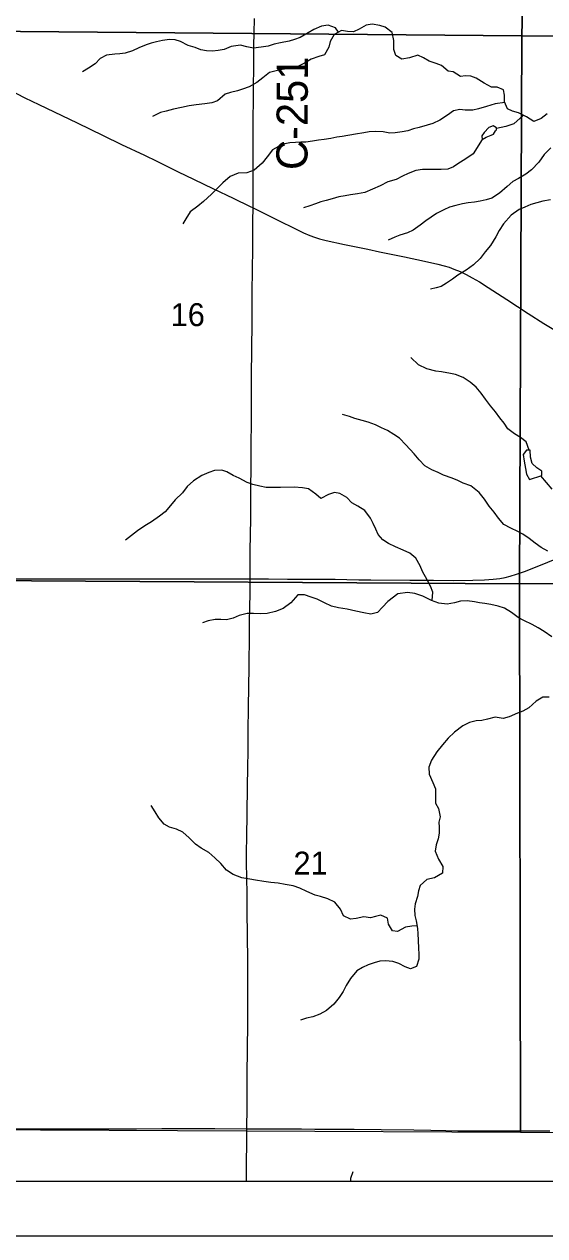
# Model space of a CAD drawing. Extents: x 0 to 34, y 0 to 22.
# Drawn here: x 13.666 to 14.616, y 9.078 to 11.289 of the extents above; entities that cross this region are included whole.
import ezdxf

# ---------------------------------------------------------------- set-up
doc = ezdxf.new("R2010")
doc.units = 0
for name, color, linetype in [('GM_X_County_Road', 7, 'Continuous'), ('GM_X_County_Road_Text', 7, 'Continuous'), ('GM_X_Minor_Lake', 7, 'Continuous'), ('GM_X_Minor_River', 7, 'Continuous'), ('GM_X_Section', 7, 'Continuous'), ('GM_X_Section_Text', 7, 'Continuous'), ('GM_X_Township_Road', 7, 'Continuous'), ('GM_X_US_Route', 7, 'Continuous'), ('SH_Data', 7, 'Continuous')]:
    doc.layers.add(name, color=color, linetype=linetype)

msp = doc.modelspace()

# ---------------------------------------------------------------- linework, layer by layer
at = {"layer": 'GM_X_County_Road'}
for points in [[(14.0833, 10.954), (14.0833, 10.9552), (14.0833, 10.9769), (14.0833, 11.0142), (14.0833, 11.0359), (14.0835, 11.0577), (14.0837, 11.0918), (14.0838, 11.1228), (14.0839, 11.1445), (14.0842, 11.1662), (14.0843, 11.1817), (14.0846, 11.2035), (14.0848, 11.2308), (14.0849, 11.2505), (14.0854, 11.2733), (14.0858, 11.2997)], [(13.4671, 11.2609), (13.4723, 11.2592), (13.478, 11.2569), (13.4823, 11.2551), (13.4923, 11.2503), (13.506, 11.243), (13.5275, 11.2307), (13.5572, 11.2137), (13.5814, 11.1998), (13.6032, 11.1878), (13.6363, 11.1705), (13.6668, 11.1552), (13.6919, 11.1429), (13.762, 11.1094), (13.8094, 11.0862), (13.843, 11.07), (13.8851, 11.05), (13.9075, 11.0392), (13.9465, 11.0201), (13.9745, 11.0065), (14.0109, 10.989), (14.0473, 10.9715), (14.078, 10.9566), (14.0833, 10.954)], [(14.0783, 10.2766), (14.0783, 10.3278), (14.079, 10.3868), (14.0791, 10.4179), (14.0793, 10.4521), (14.0796, 10.4707), (14.0798, 10.4893), (14.0799, 10.5204), (14.0804, 10.5638), (14.0806, 10.6011), (14.0806, 10.6477), (14.0815, 10.7441), (14.0817, 10.772), (14.0818, 10.8), (14.0827, 10.8807), (14.083, 10.9304), (14.0833, 10.954)], [(14.0833, 10.954), (14.1142, 10.9389), (14.1756, 10.9088), (14.187, 10.9036), (14.1958, 10.9003), (14.2047, 10.8976), (14.2168, 10.8945), (14.2503, 10.8875), (14.2928, 10.8784), (14.314, 10.8738), (14.3597, 10.8645), (14.3962, 10.8569), (14.4204, 10.8515), (14.4324, 10.8484), (14.4413, 10.8456), (14.45, 10.8424), (14.4614, 10.8377), (14.4726, 10.8324), (14.4836, 10.8266), (14.4969, 10.8188), (14.5127, 10.8089), (14.5465, 10.7868), (14.5856, 10.7615), (14.6144, 10.7431), (14.6356, 10.7301)], [(14.0721, 9.273), (14.0723, 9.3126), (14.0725, 9.3436), (14.0726, 9.3716), (14.0736, 9.4648), (14.0737, 9.5052), (14.0738, 9.5394), (14.0735, 9.5735), (14.073, 9.6326), (14.0728, 9.6636), (14.0725, 9.6978), (14.0722, 9.7351), (14.0716, 9.7546), (14.0714, 9.7768), (14.0718, 9.8073), (14.0723, 9.8469), (14.0731, 9.8997), (14.0737, 9.9307), (14.0742, 9.9649), (14.0746, 9.999), (14.0752, 10.0425), (14.0757, 10.0797), (14.0761, 10.1153), (14.0763, 10.1353), (14.0766, 10.1572), (14.0768, 10.1775), (14.0771, 10.2012), (14.0774, 10.2222), (14.078, 10.2533), (14.0783, 10.275), (14.0783, 10.2766)], [(14.0713, 9.1775), (14.0713, 9.179), (14.0716, 9.2163), (14.0719, 9.2412), (14.0721, 9.2691), (14.0721, 9.273)]]:
    msp.add_lwpolyline(points, dxfattribs=at)
at = {"layer": 'GM_X_Minor_Lake'}
for points in [[(14.6107, 10.4654), (14.6107, 10.4733), (14.6012, 10.4794), (14.5928, 10.4877), (14.5902, 10.4991), (14.589, 10.512), (14.5829, 10.5116), (14.5765, 10.504), (14.5784, 10.4918), (14.5807, 10.4782), (14.5827, 10.4679), (14.588, 10.4581)], [(14.588, 10.4581), (14.6107, 10.4654)]]:
    msp.add_lwpolyline(points, dxfattribs=at)
at = {"layer": 'GM_X_Minor_River'}
for points in [[(14.2395, 11.275), (14.2336, 11.2827), (14.2203, 11.2875), (14.2081, 11.286), (14.1941, 11.2799), (14.1839, 11.2734), (14.1695, 11.2654), (14.1589, 11.2612), (14.1494, 11.2585), (14.1335, 11.2554), (14.1221, 11.2527), (14.1111, 11.2496), (14.0982, 11.2473), (14.0842, 11.2454), (14.0721, 11.248), (14.0603, 11.251), (14.0436, 11.2487), (14.0307, 11.2433), (14.0197, 11.2414), (14.0095, 11.2399), (13.9985, 11.2406), (13.9879, 11.2428), (13.9776, 11.247), (13.9651, 11.2507), (13.9506, 11.2579), (13.9412, 11.2609), (13.9305, 11.2612), (13.918, 11.2597), (13.907, 11.2574), (13.8975, 11.2547), (13.8881, 11.252), (13.8748, 11.2463), (13.8631, 11.2409), (13.8498, 11.2367), (13.8403, 11.2352), (13.8308, 11.2344), (13.816, 11.2328), (13.8039, 11.2267), (13.7952, 11.2172), (13.7831, 11.2092), (13.7718, 11.2023)], [(14.3946, 11.2277), (14.3839, 11.233), (14.3688, 11.2277), (14.3547, 11.2257), (14.3441, 11.2325), (14.3403, 11.2431), (14.3402, 11.2598), (14.3375, 11.2742), (14.3246, 11.2837), (14.3147, 11.2871), (14.3007, 11.2893), (14.2901, 11.2874), (14.2768, 11.2801), (14.267, 11.2752), (14.256, 11.2763), (14.2446, 11.2778), (14.2313, 11.2705), (14.2242, 11.258), (14.2215, 11.2473), (14.214, 11.2336), (14.2034, 11.2302), (14.1894, 11.2256), (14.1772, 11.218), (14.164, 11.2115), (14.15, 11.2088), (14.1367, 11.2065), (14.1253, 11.2042), (14.1136, 11.2011), (14.1011, 11.1916), (14.0905, 11.1832), (14.0765, 11.1748), (14.0643, 11.1706), (14.0549, 11.1679), (14.0423, 11.1648), (14.0325, 11.1614), (14.0185, 11.1492), (14.0083, 11.1458), (13.995, 11.1438), (13.9794, 11.1422), (13.9665, 11.1403), (13.9529, 11.1376), (13.9381, 11.1342), (13.9248, 11.1307), (13.9142, 11.128), (13.8995, 11.1208)], [(14.6206, 11.1256), (14.6092, 11.1172), (14.596, 11.1119), (14.5823, 11.1202), (14.5678, 11.1273), (14.5572, 11.1307), (14.5477, 11.1349), (14.5427, 11.1474), (14.5427, 11.1599), (14.5404, 11.1694), (14.529, 11.1747), (14.5184, 11.1742), (14.5055, 11.1818), (14.491, 11.1909), (14.4808, 11.1946), (14.4713, 11.195), (14.4618, 11.1942), (14.4489, 11.2025), (14.4394, 11.2036), (14.4272, 11.2142), (14.4174, 11.2176), (14.4048, 11.2217), (14.3946, 11.2277)], [(14.5431, 11.1464), (14.5253, 11.1443), (14.5094, 11.1393), (14.495, 11.1347), (14.4848, 11.1324), (14.4707, 11.1327), (14.4609, 11.1335), (14.4495, 11.1315), (14.4381, 11.1235), (14.4245, 11.1144), (14.4116, 11.1079), (14.401, 11.1048), (14.3866, 11.101), (14.3764, 11.0983), (14.3658, 11.0949), (14.3555, 11.0929), (14.3426, 11.091), (14.3331, 11.0906), (14.3206, 11.0928), (14.3066, 11.0935), (14.2956, 11.0927), (14.2853, 11.0912), (14.2706, 11.0885), (14.2463, 11.0846), (14.2364, 11.0831), (14.2251, 11.0808), (14.2133, 11.0788), (14.2031, 11.0777), (14.1917, 11.0757), (14.1799, 11.0742), (14.1704, 11.0741), (14.161, 11.0737), (14.1507, 11.073), (14.1412, 11.071), (14.1295, 11.0664), (14.1189, 11.06), (14.1091, 11.0474), (14.1, 11.036), (14.0856, 11.023), (14.072, 11.0181), (14.0564, 11.0173), (14.0417, 11.0115), (14.028, 10.9997), (14.0174, 10.9887), (14.0072, 10.9788), (13.9929, 10.9659), (13.9826, 10.9571), (13.9686, 10.9468), (13.9607, 10.9343), (13.955, 10.9248)], [(14.5281, 11.1003), (14.5216, 11.1037), (14.5137, 11.1006), (14.5054, 11.0919), (14.5008, 11.0858), (14.5016, 11.079), (14.5088, 11.0831), (14.5183, 11.087), (14.5224, 11.0885), (14.5258, 11.0946)], [(14.5767, 11.1229), (14.5592, 11.1076), (14.5448, 11.1026), (14.528, 11.0989)], [(14.5258, 11.0946), (14.5278, 11.0966), (14.528, 11.0977), (14.5281, 11.1003)], [(14.5016, 11.079), (14.485, 11.0527), (14.4702, 11.0424), (14.4592, 11.0359), (14.4494, 11.0291), (14.4388, 11.0245), (14.4267, 11.0241), (14.4164, 11.0241), (14.405, 11.0244), (14.3929, 11.024), (14.3808, 11.0224), (14.3664, 11.0171), (14.3561, 11.0117), (14.3444, 11.006), (14.3296, 11.0018), (14.3156, 10.9945), (14.3012, 10.9884), (14.2872, 10.9819), (14.2739, 10.9796), (14.261, 10.9777), (14.2515, 10.9761), (14.2402, 10.9742), (14.2277, 10.9707), (14.2167, 10.9677), (14.2068, 10.965), (14.1973, 10.9615), (14.1871, 10.9577), (14.1757, 10.9543)], [(14.6268, 11.0638), (14.6151, 11.0516), (14.6053, 11.0375), (14.592, 11.0238), (14.5811, 11.0158), (14.5682, 11.0078), (14.5576, 11.0025), (14.547, 10.9933), (14.533, 10.9808), (14.519, 10.972), (14.5088, 10.9686), (14.4981, 10.9663), (14.4875, 10.9647), (14.4758, 10.9635), (14.4655, 10.9616), (14.4534, 10.9585), (14.442, 10.9555), (14.4318, 10.9505), (14.4185, 10.944), (14.4087, 10.9371), (14.3985, 10.9307), (14.3883, 10.9223), (14.3758, 10.9135), (14.3655, 10.9086), (14.3515, 10.904), (14.342, 10.9005), (14.3299, 10.8952)], [(14.6263, 10.9689), (14.6127, 10.9662), (14.6013, 10.9635), (14.5907, 10.9601), (14.5793, 10.9551), (14.5691, 10.9513), (14.5544, 10.9406), (14.5407, 10.925), (14.5328, 10.9129), (14.5268, 10.9015), (14.517, 10.8855), (14.5071, 10.8741), (14.4977, 10.8615), (14.486, 10.8501), (14.4723, 10.8402), (14.4572, 10.8314), (14.4473, 10.8242), (14.4367, 10.8166), (14.4269, 10.8108), (14.4174, 10.8082), (14.4076, 10.8059)], [(14.5876, 10.5119), (14.5817, 10.5271), (14.5718, 10.5347), (14.5608, 10.5415), (14.5487, 10.5505), (14.5418, 10.5611), (14.5338, 10.571), (14.5258, 10.582), (14.5167, 10.5926), (14.5079, 10.6051), (14.4999, 10.6157), (14.4904, 10.6266), (14.4798, 10.6361), (14.4668, 10.6444), (14.4532, 10.6497), (14.4437, 10.6515), (14.4277, 10.6545), (14.4171, 10.656), (14.4004, 10.6605), (14.3856, 10.6677), (14.3711, 10.6809)], [(14.6218, 10.3273), (14.6092, 10.3341), (14.5982, 10.342), (14.5872, 10.3507), (14.5762, 10.3583), (14.5667, 10.3632), (14.5537, 10.3692), (14.5412, 10.376), (14.5317, 10.3877), (14.5237, 10.3983), (14.5146, 10.4097), (14.5058, 10.4225), (14.4963, 10.4347), (14.4811, 10.4464), (14.467, 10.4516), (14.4571, 10.4562), (14.4469, 10.4607), (14.4313, 10.4663), (14.4211, 10.4709), (14.4097, 10.4761), (14.3967, 10.4829), (14.3865, 10.4943), (14.3773, 10.5049), (14.3625, 10.5215), (14.3507, 10.5336), (14.3404, 10.5404), (14.329, 10.5476), (14.3176, 10.5525), (14.307, 10.5578), (14.2933, 10.563), (14.2827, 10.5657), (14.2694, 10.5694), (14.2595, 10.5732), (14.2466, 10.5766)], [(14.4105, 10.237), (14.4118, 10.2527), (14.4076, 10.2633), (14.4011, 10.275), (14.3928, 10.2905), (14.3882, 10.3004), (14.3805, 10.3144), (14.3695, 10.3239), (14.3574, 10.3291), (14.3437, 10.3352), (14.3304, 10.3416), (14.3205, 10.348), (14.3118, 10.3578), (14.3072, 10.3677), (14.3026, 10.3779), (14.298, 10.3878), (14.2874, 10.4014), (14.2744, 10.4097), (14.2634, 10.4154), (14.2543, 10.4256), (14.2417, 10.4327), (14.2323, 10.4342), (14.2213, 10.4308), (14.2072, 10.4232), (14.1977, 10.4315), (14.1848, 10.4409), (14.1738, 10.4432), (14.1583, 10.4439), (14.1336, 10.4438), (14.1196, 10.4434), (14.107, 10.4437), (14.0957, 10.446), (14.0827, 10.4493), (14.0725, 10.4527), (14.0577, 10.4606), (14.047, 10.4655), (14.0356, 10.4723), (14.0261, 10.4753), (14.0129, 10.4749), (14.0023, 10.4707), (13.9898, 10.4654), (13.9746, 10.4555), (13.9633, 10.4456), (13.9542, 10.4338), (13.9413, 10.4208), (13.9326, 10.4106), (13.9228, 10.3991), (13.9122, 10.3911), (13.8978, 10.3812), (13.8857, 10.3736), (13.8721, 10.3645), (13.8611, 10.3561), (13.8505, 10.3477)], [(14.6294, 10.4404), (14.6086, 10.4647)], [(14.6287, 10.171), (14.615, 10.1808), (14.6036, 10.1872), (14.5929, 10.1936), (14.5778, 10.2008), (14.5675, 10.2061), (14.5553, 10.2155), (14.5424, 10.2235), (14.5306, 10.2272), (14.5174, 10.2298), (14.5063, 10.2317), (14.4969, 10.2332), (14.4874, 10.2351), (14.4745, 10.2365), (14.4623, 10.2361), (14.4513, 10.233), (14.4377, 10.2307), (14.4225, 10.2326), (14.4092, 10.2375), (14.3933, 10.245), (14.3785, 10.2503), (14.3652, 10.2521), (14.3477, 10.2494), (14.3292, 10.2357), (14.3197, 10.2254), (14.3103, 10.2155), (14.2985, 10.2125), (14.2856, 10.2147), (14.2708, 10.2181), (14.2553, 10.2214), (14.2393, 10.2241), (14.2268, 10.2267), (14.2135, 10.2331), (14.2006, 10.2395), (14.1892, 10.2436), (14.1774, 10.2478), (14.1649, 10.2477), (14.152, 10.2333), (14.1384, 10.2226), (14.1244, 10.2173), (14.1088, 10.2138), (14.0975, 10.213), (14.0842, 10.2133), (14.0728, 10.2137), (14.058, 10.2098), (14.047, 10.2049), (14.0349, 10.2022), (14.0247, 10.2025), (14.014, 10.2025), (14.0015, 10.2002), (13.9909, 10.1964)], [(14.6241, 10.0606), (14.6127, 10.0609), (14.6002, 10.0533), (14.5866, 10.0415), (14.576, 10.0354), (14.5661, 10.0315), (14.551, 10.025), (14.54, 10.0216), (14.5255, 10.0242), (14.5111, 10.0204), (14.5013, 10.0181), (14.4907, 10.0176), (14.4785, 10.0146), (14.4664, 10.0085), (14.4513, 9.997), (14.4395, 9.986), (14.4293, 9.9738), (14.4188, 9.9609), (14.4089, 9.9457), (14.4044, 9.9332), (14.4048, 9.9203), (14.4117, 9.9051), (14.4167, 9.8937), (14.4167, 9.8793), (14.4164, 9.8672), (14.4217, 9.8573), (14.4252, 9.8422), (14.4225, 9.8327), (14.4229, 9.8232), (14.4234, 9.8126), (14.4211, 9.8019), (14.4177, 9.7913), (14.4159, 9.7795), (14.422, 9.7651), (14.4296, 9.7515), (14.4293, 9.7393), (14.4149, 9.7309), (14.4005, 9.7279), (14.3887, 9.7172), (14.3853, 9.7073), (14.3835, 9.6971), (14.3793, 9.6838), (14.3779, 9.6739), (14.379, 9.6622), (14.381, 9.6523), (14.3833, 9.6387), (14.3844, 9.6288), (14.3849, 9.6174), (14.3857, 9.6022), (14.3861, 9.592), (14.3861, 9.5825), (14.382, 9.5692), (14.371, 9.5646), (14.3611, 9.5688), (14.3497, 9.5748), (14.3383, 9.5782), (14.3254, 9.5793), (14.3148, 9.5789), (14.3042, 9.5758), (14.2936, 9.572), (14.283, 9.567), (14.2731, 9.5609), (14.261, 9.5472)], [(14.3824, 9.6435), (14.3734, 9.6428), (14.3616, 9.6409), (14.3472, 9.6332), (14.3378, 9.6343), (14.3305, 9.6465), (14.329, 9.6575), (14.3168, 9.6631), (14.307, 9.6604), (14.2975, 9.6581), (14.2853, 9.6596), (14.2717, 9.6569), (14.2615, 9.6557), (14.2482, 9.6614), (14.2428, 9.6735), (14.2329, 9.6864), (14.2196, 9.6928), (14.2067, 9.6969), (14.1968, 9.6996), (14.1813, 9.706), (14.1687, 9.7124), (14.1566, 9.7161), (14.1422, 9.7191), (14.1293, 9.721), (14.116, 9.7225), (14.1031, 9.7243), (14.0879, 9.7265), (14.0773, 9.7284), (14.0628, 9.731), (14.0473, 9.737), (14.0351, 9.745), (14.0244, 9.7571), (14.0134, 9.7677), (14.0024, 9.7771), (13.9883, 9.7854), (13.9781, 9.7922), (13.9666, 9.8043), (13.9549, 9.8145), (13.9438, 9.8198), (13.9309, 9.8236), (13.9211, 9.8292), (13.9115, 9.8406), (13.9047, 9.8512), (13.8974, 9.8629)], [(14.261, 9.5472), (14.2531, 9.5343), (14.2478, 9.5237), (14.2406, 9.5126), (14.2308, 9.5005), (14.2176, 9.4887), (14.2054, 9.4818), (14.1922, 9.4772), (14.1812, 9.4745), (14.1702, 9.4714)], [(14.2616, 9.1775), (14.2621, 9.1826), (14.2662, 9.1948)]]:
    msp.add_lwpolyline(points, dxfattribs=at)
at = {"layer": 'GM_X_Section'}
for points in [[(13.6043, 12.2869), (14.5977, 12.2808), (14.5738, 11.2682), (13.5876, 11.2769)], [(15.5907, 12.2877), (15.569, 11.2675), (14.5738, 11.2682), (14.5977, 12.2808), (15.0525, 12.2941)], [(13.5876, 11.2769), (14.5738, 11.2682), (14.5701, 10.2676), (13.5789, 10.274)], [(14.5738, 11.2682), (15.569, 11.2675), (15.5602, 10.3325), (15.0726, 10.2709), (14.5701, 10.2676)], [(14.5701, 10.2676), (15.0726, 10.2709), (15.5602, 10.3325), (15.5576, 9.3334), (15.0625, 9.2635), (14.5716, 9.2663)], [(13.5789, 10.274), (14.5701, 10.2676), (14.5716, 9.2663), (13.5692, 9.2712)]]:
    msp.add_lwpolyline(points, close=True, dxfattribs=at)
at = {"layer": 'GM_X_Township_Road'}
for points in [[(13.6406, 9.2727), (13.684, 9.2728), (13.7275, 9.2729), (13.771, 9.2728), (13.8083, 9.2726), (13.8362, 9.2726), (13.8704, 9.2729), (13.917, 9.2733), (13.9605, 9.2735), (13.9791, 9.2735), (14.0133, 9.2732), (14.0721, 9.273)], [(14.0721, 9.273), (14.0784, 9.2729), (14.0877, 9.2729), (14.1095, 9.2729), (14.1281, 9.2726), (14.1467, 9.2725), (14.1592, 9.2726), (14.1716, 9.2727), (14.1964, 9.2724), (14.2088, 9.2723), (14.2336, 9.2722), (14.2678, 9.2721), (14.3175, 9.2717), (14.3766, 9.271), (14.4077, 9.2704), (14.4356, 9.2697), (14.4574, 9.2694), (14.4822, 9.2692), (14.5225, 9.2692), (14.5753, 9.2692), (14.625, 9.2693)]]:
    msp.add_lwpolyline(points, dxfattribs=at)
at = {"layer": 'GM_X_US_Route'}
for points in [[(14.0931, 10.2766), (14.1118, 10.2766), (14.146, 10.2764), (14.1708, 10.2763), (14.1957, 10.2762), (14.233, 10.276), (14.2547, 10.2756), (14.2765, 10.2753), (14.2982, 10.2753), (14.3695, 10.2746), (14.3912, 10.2745), (14.4129, 10.2746), (14.4502, 10.2741), (14.4844, 10.2744), (14.5062, 10.275), (14.5218, 10.2761), (14.5342, 10.2776), (14.5434, 10.2793), (14.5525, 10.2815), (14.5644, 10.2852), (14.5791, 10.2904), (14.608, 10.3019), (14.6455, 10.3168)], [(13.6488, 10.277), (13.711, 10.2766), (13.8322, 10.2769), (13.8695, 10.2769), (13.9347, 10.2767), (13.972, 10.277), (14.0186, 10.2769), (14.0715, 10.2766), (14.0783, 10.2766), (14.0931, 10.2766)]]:
    msp.add_lwpolyline(points, dxfattribs=at)
at = {"layer": 'SH_Data'}
for p, q in [((9.1079, 9.1775), (15.9079, 9.1775)), ((9.0079, 9.0775), (16.0079, 9.0775))]:
    msp.add_line(p, q, dxfattribs=at)

# ---------------------------------------------------------------- texts
at = {"layer": 'GM_X_County_Road_Text'}
msp.add_text('C-251', height=0.05682, rotation=89.7323, dxfattribs=at).set_placement((14.1826, 11.0231))
at = {"layer": 'GM_X_Section_Text'}
for s, p in [('16', (13.933, 10.7382)), ('21', (14.1572, 9.7369))]:
    msp.add_text(s, height=0.04186, rotation=0, dxfattribs=at).set_placement(p)

doc.saveas('drawing.dxf')
